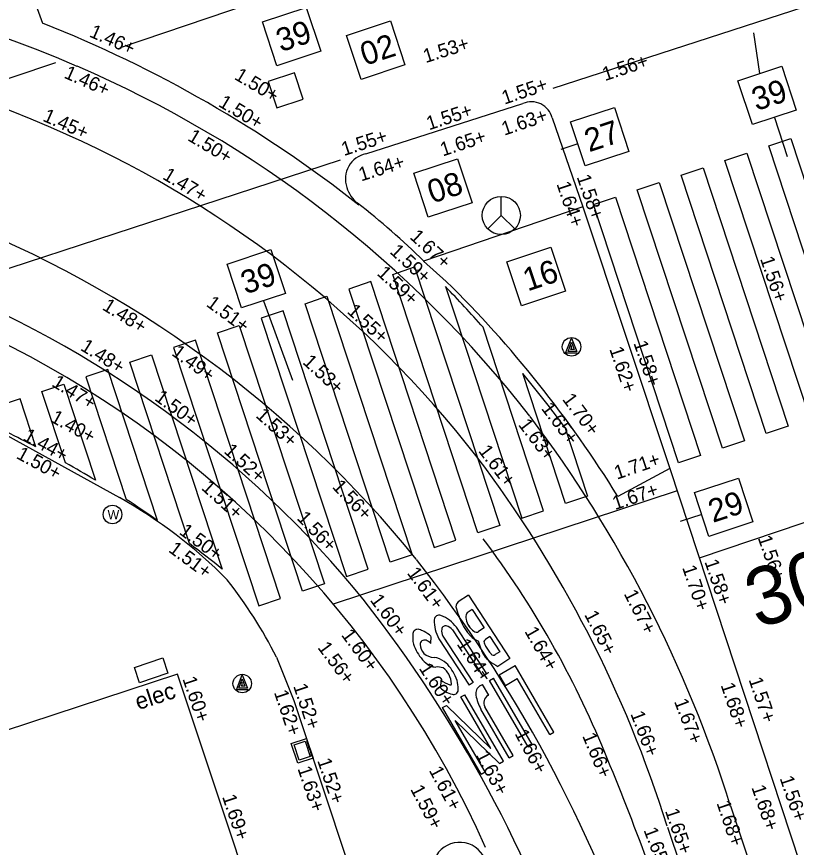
# Model space of a CAD drawing. Extents: x 122462 to 123306, y 485548 to 486417.
# Drawn here: x 122804.23 to 122821.1, y 486155.15 to 486173.11 of the extents above; entities that cross this region are included whole.
import ezdxf

# ---------------------------------------------------------------- set-up
doc = ezdxf.new("R2010")
doc.units = 0
for name, color, linetype in [('B-WE-IE-MEUBILAIR_ELECTRAKAST', 7, 'Continuous'), ('B-WE-OG-HOOGTEPUNT-S', 7, 'Continuous'), ('B-WE-OG-TOPOKAART-G', 7, 'Continuous'), ('iba7-verkeersbord blauw', 7, 'Continuous'), ('V markering 1-1 10 cm', 7, 'Continuous'), ('V markering figuratie', 7, 'Continuous'), ('V markering haaientanden', 7, 'Continuous'), ('V markering ononderbroken streep 10 cm', 7, 'Continuous'), ('V materiaalscheiding algemeen', 7, 'Continuous'), ('V meubilair ANWB paal', 7, 'Continuous'), ('V meubilair verkeersbord', 7, 'Continuous'), ('V Rails', 7, 'Continuous'), ('V riool putdeksel', 7, 'Continuous'), ('V riool trottoirkolk', 7, 'Continuous'), ('V RWS-band 115-225x250 mm specie', 7, 'Continuous'), ('V trottoirband 180-200x250 mm specie', 7, 'Continuous'), ('X-WE-AL-TEKENBLAD-S', 7, 'Continuous')]:
    doc.layers.add(name, color=color, linetype=linetype)

msp = doc.modelspace()

# ---------------------------------------------------------------- linework, layer by layer
at = {"layer": 'B-WE-IE-MEUBILAIR_ELECTRAKAST'}
for p, q in [((122806.779, 486159.039), (122807.397, 486159.243)), ((122807.397, 486159.243), (122807.505, 486158.911)), ((122806.888, 486158.707), (122806.779, 486159.039)), ((122807.505, 486158.911), (122806.888, 486158.707))]:
    msp.add_line(p, q, dxfattribs=at)
at = {"layer": 'B-WE-OG-TOPOKAART-G'}
msp.add_lwpolyline([(122810.445, 486142.778), (122812.82, 486143.569), (122807.709, 486158.89), (122801.277, 486156.78)], dxfattribs=at)
at = {"layer": 'iba7-verkeersbord blauw'}
msp.add_circle((122806.305, 486162.345), 0.2, dxfattribs=at)
at = {"layer": 'V markering 1-1 10 cm'}
msp.add_lwpolyline([(122811.233, 486170.007), (122798.828, 486165.954)], dxfattribs=at)
at = {"layer": 'V markering figuratie'}
for p, q in [((122814.005, 486160.601), (122813.781, 486160.455)), ((122814.005, 486160.601), (122814.903, 486159.228)), ((122814.089, 486160.288), (122813.981, 486160.218)), ((122814.089, 486160.288), (122814.347, 486159.893)), ((122813.743, 486159.905), (122814.4, 486158.901)), ((122814.347, 486159.893), (122814.226, 486159.814)), ((122813.191, 486159.556), (122813.196, 486159.71)), ((122813.452, 486159.714), (122814.108, 486158.709)), ((122813.66, 486159.851), (122814.317, 486158.847)), ((122814.471, 486159.704), (122814.372, 486159.639)), ((122814.471, 486159.704), (122814.682, 486159.378)), ((122813.368, 486159.659), (122814.024, 486158.654)), ((122814.682, 486159.378), (122814.587, 486159.316)), ((122814.903, 486159.228), (122814.645, 486159.06)), ((122814.669, 486158.881), (122815.013, 486159.08)), ((122815.85, 486157.64), (122815.013, 486159.08)), ((122814.4, 486158.901), (122814.317, 486158.847)), ((122814.459, 486158.758), (122814.545, 486158.808)), ((122815.382, 486157.368), (122814.545, 486158.808)), ((122814.805, 486158.647), (122814.669, 486158.881)), ((122814.805, 486158.647), (122815.063, 486158.797)), ((122815.765, 486157.59), (122815.063, 486158.797)), ((122813.406, 486158.764), (122813.398, 486158.595)), ((122814.108, 486158.709), (122814.024, 486158.654)), ((122814.264, 486158.645), (122814.309, 486158.671)), ((122814.445, 486158.438), (122814.309, 486158.671)), ((122815.297, 486157.318), (122814.459, 486158.758)), ((122813.841, 486158.399), (122813.926, 486158.448)), ((122814.763, 486157.008), (122813.926, 486158.448)), ((122814.426, 486158.427), (122814.445, 486158.438)), ((122814.49, 486157.282), (122813.841, 486158.399)), ((122813.445, 486158.169), (122813.528, 486158.217)), ((122814.282, 486156.728), (122813.445, 486158.169)), ((122814.49, 486157.282), (122813.528, 486158.217)), ((122814.89, 486157.081), (122814.277, 486158.136)), ((122814.975, 486157.131), (122814.362, 486158.186)), ((122814.68, 486156.959), (122813.72, 486157.892)), ((122814.368, 486156.778), (122813.72, 486157.892)), ((122815.765, 486157.59), (122815.85, 486157.64)), ((122815.297, 486157.318), (122815.382, 486157.368)), ((122814.68, 486156.959), (122814.763, 486157.008)), ((122814.89, 486157.081), (122814.975, 486157.131)), ((122814.282, 486156.728), (122814.368, 486156.778))]:
    msp.add_line(p, q, dxfattribs=at)
for points in [[(122822.346, 486164.731), (122820.504, 486170.318), (122820.978, 486170.476), (122822.82, 486164.889)], [(122821.398, 486164.414), (122819.555, 486170.001), (122820.03, 486170.159), (122821.872, 486164.572)], [(122820.449, 486164.097), (122818.607, 486169.684), (122819.081, 486169.842), (122820.923, 486164.255)], [(122819.501, 486163.78), (122817.658, 486169.367), (122818.133, 486169.525), (122819.975, 486163.938)], [(122818.552, 486163.463), (122816.71, 486169.05), (122817.184, 486169.208), (122819.026, 486163.621)], [(122814.21, 486161.951), (122812.368, 486167.538), (122812.842, 486167.697), (122814.685, 486162.11)], [(122811.42, 486167.221), (122813.262, 486161.634), (122813.736, 486161.793), (122811.894, 486167.38)], [(122812.313, 486161.317), (122810.471, 486166.904), (122810.945, 486167.063), (122812.788, 486161.476)], [(122809.523, 486166.588), (122811.365, 486161.001), (122811.839, 486161.159), (122809.997, 486166.746)], [(122810.416, 486160.684), (122808.574, 486166.271), (122809.049, 486166.429), (122810.891, 486160.842)], [(122807.626, 486165.954), (122809.468, 486160.367), (122809.942, 486160.525), (122808.1, 486166.112)]]:
    msp.add_lwpolyline(points, close=True, dxfattribs=at)
for points in [[(122813.508, 486167.274), (122815.159, 486162.268), (122815.633, 486162.427), (122814.325, 486166.394)], [(122807.97, 486161.717), (122806.677, 486165.637), (122807.152, 486165.795), (122808.679, 486161.162)], [(122807.278, 486162.218), (122806.203, 486165.478), (122805.729, 486165.32), (122806.602, 486162.672)], [(122816.091, 486164.231), (122816.581, 486162.744), (122816.107, 486162.585), (122815.181, 486165.394)], [(122805.288, 486163.464), (122804.78, 486165.003), (122805.255, 486165.161), (122805.939, 486163.086)], [(122804.647, 486163.81), (122804.306, 486164.844), (122803.832, 486164.686), (122804.017, 486164.126)]]:
    msp.add_lwpolyline(points, dxfattribs=at)
for centre, radius, start, end in [((122790.834, 486145.409), 31.499, 41.7743, 43.9578), ((122790.834, 486145.409), 31.499, 36.6934, 39.3801), ((122793.654, 486142.673), 23.824, 62.5212, 64.2182), ((122793.654, 486142.673), 23.824, 58.9603, 60.771), ((122793.654, 486142.673), 23.824, 55.1209, 57.0806), ((122793.654, 486142.673), 23.824, 50.9021, 53.0674), ((122813.866, 486160.355), 0.13, 130.2044, 201.7441), ((122815.938, 486160.955), 2.287, 196.4523, 201.7405), ((122813.964, 486160.022), 0.698, 176.115, 211.3596), ((122813.375, 486160.059), 0.109, 72.1477, 174.6458), ((122813.171, 486159.506), 0.698, 34.8339, 70.0785), ((122815.334, 486160.69), 1.628, 200.9537, 208.2212), ((122814.15, 486160.119), 0.199, 153.3445, 191.8719), ((122814.394, 486160.172), 0.448, 192.1555, 212.2665), ((122813.996, 486160.196), 0.0256, 123.4302, 153.3445), ((122813.508, 486159.856), 0.0816, 71.44, 175.2165), ((122813.476, 486159.708), 0.233, 37.7791, 75.6405), ((122814.889, 486160.507), 1.15, 210.6597, 220.942), ((122814.433, 486160.226), 0.51, 214.9747, 232.6342), ((122813.394, 486159.684), 0.595, 171.6022, 193.6008), ((122812.906, 486159.761), 0.101, 72.0219, 174.3362), ((122812.848, 486159.483), 0.384, 58.7817, 76.6476), ((122812.648, 486159.071), 0.842, 49.4271, 61.6531), ((122813.657, 486159.824), 0.233, 170.2725, 208.1339), ((122814.359, 486160.014), 0.428, 217.5747, 251.9484), ((122814.179, 486159.884), 0.0849, 229.3337, 303.5616), ((122813.623, 486159.797), 0.846, 197.3862, 210.8175), ((122813.057, 486159.534), 0.0964, 71.3983, 180.6349), ((122813.268, 486159.548), 0.307, 182.7741, 222.2592), ((122812.941, 486159.295), 0.362, 46.2045, 65.9719), ((122811.982, 486158.843), 2.37, 14.4022, 18.7882), ((122814.408, 486159.582), 0.0675, 121.909, 167.7229), ((122814.805, 486159.706), 0.476, 193.2255, 205.8502), ((122813.737, 486159.855), 0.974, 210.3227, 221.8314), ((122813.28, 486159.617), 0.365, 228.9599, 267.1101), ((122814.75, 486159.577), 0.493, 196.9472, 233.3), ((122815.001, 486159.804), 0.695, 206.1216, 223.2043), ((122813.505, 486159.63), 0.651, 220.7065, 238.69), ((122813.224, 486158.841), 0.413, 51.2717, 84.7982), ((122813.064, 486158.612), 0.692, 36.3276, 52.8145), ((122815.282, 486160.268), 1.366, 232.7346, 242.199), ((122814.548, 486159.373), 0.0697, 220.2342, 304.4683), ((122813.299, 486159.368), 0.322, 245.8091, 270.6339), ((122813.335, 486158.697), 0.35, 69.7297, 95.3518), ((122813.288, 486158.745), 0.327, 24.6134, 59.0664), ((122812.829, 486158.444), 0.981, 24.6208, 36.0826), ((122813.111, 486158.635), 0.534, 5.4213, 27.3838), ((122813.209, 486158.596), 0.573, 6.1755, 26.6295), ((122813.811, 486159.292), 0.666, 232.4802, 251.7493), ((122813.612, 486158.689), 0.0305, 251.2599, 354.9973), ((122813.204, 486158.571), 0.581, 357.2377, 8.5295), ((122814.364, 486158.471), 0.201, 120.1695, 190.1275), ((122813.843, 486159.107), 0.678, 229.0189, 240.597), ((122813.883, 486159.224), 0.8, 242.2305, 253.2995), ((122813.686, 486158.551), 0.0987, 250.6138, 355.6868), ((122815.069, 486158.597), 0.916, 190.1289, 210.1695), ((122814.515, 486158.275), 0.176, 120.1695, 210.1695)]:
    msp.add_arc(centre, radius, start, end, dxfattribs=at)
at = {"layer": 'V markering haaientanden'}
for points in [[(122815.839, 486171.566), (122825.165, 486174.59)], [(122809.772, 486173.563), (122806.472, 486172.433)]]:
    msp.add_lwpolyline(points, dxfattribs=at)
at = {"layer": 'V markering ononderbroken streep 10 cm'}
msp.add_lwpolyline([(122796.786, 486169.34), (122805.08, 486172.122)], dxfattribs=at)
for centre, radius, start, end in [((122797.619, 486149.245), 20.91, 22.3632, 36.9681), ((122746.081, 486128.041), 76.639, 18.61709, 22.36324)]:
    msp.add_arc(centre, radius, start, end, dxfattribs=at)
at = {"layer": 'V materiaalscheiding algemeen'}
msp.add_line((122818.523, 486162.855), (122811.081, 486160.409), dxfattribs=at)
for points in [[(122820.373, 486178.699), (122819.656, 486178.534), (122819.692, 486178.438), (122804.62, 486173.448), (122804.792, 486172.968)], [(122819.003, 486161.406), (122821.801, 486162.349)]]:
    msp.add_lwpolyline(points, dxfattribs=at)
for centre, radius, start, end in [((122794.859, 486147.77), 27.085, 51.7216, 68.4862), ((122793.815, 486145.927), 22.535, 24.1472, 99.0789)]:
    msp.add_arc(centre, radius, start, end, dxfattribs=at)
at = {"layer": 'V meubilair ANWB paal'}
for q in [(122814.716, 486169.224), (122814.424, 486168.519), (122815.008, 486168.519)]:
    msp.add_line((122814.716, 486168.811), q, dxfattribs=at)
msp.add_circle((122814.716, 486168.811), 0.413, dxfattribs=at)
at = {"layer": 'V meubilair verkeersbord'}
for points in [[(122816.361, 486165.833), (122816.109, 486165.833), (122816.236, 486166.156), (122816.35, 486165.871), (122816.165, 486165.871), (122816.236, 486166.071), (122816.292, 486165.911), (122816.223, 486165.911), (122816.236, 486165.951), (122816.237, 486166.001)], [(122809.237, 486158.551), (122808.985, 486158.551), (122809.112, 486158.874), (122809.226, 486158.589), (122809.041, 486158.589), (122809.112, 486158.789), (122809.168, 486158.629), (122809.099, 486158.629), (122809.112, 486158.669), (122809.113, 486158.719)]]:
    msp.add_lwpolyline(points, dxfattribs=at)
for centre in [(122816.236, 486165.971), (122809.112, 486158.689)]:
    msp.add_circle(centre, 0.2, dxfattribs=at)
at = {"layer": 'V Rails'}
for p, q in [((122819.673, 486156.047), (122836.339, 486106.728)), ((122818.309, 486155.586), (122834.974, 486106.268))]:
    msp.add_line(p, q, dxfattribs=at)
for centre, radius, start, end in [((122795.822, 486149.654), 24.402, 66.5251, 103.0007), ((122795.822, 486149.654), 22.962, 66.5251, 103.0007), ((122795.758, 486149.261), 24.788, 37.8464, 66.7583), ((122795.758, 486149.261), 23.348, 37.8464, 66.7583), ((122793.991, 486146.126), 24.276, 38.9361, 68.8275), ((122793.991, 486146.126), 22.836, 38.9361, 68.8275), ((122793.305, 486147.787), 27.632, 17.3592, 37.1191), ((122793.305, 486147.787), 26.192, 17.3592, 37.1191), ((122789.32, 486142.851), 29.97, 18.4811, 38.1761), ((122789.32, 486142.851), 28.53, 18.4811, 38.1761)]:
    msp.add_arc(centre, radius, start, end, dxfattribs=at)
at = {"layer": 'V riool putdeksel'}
msp.add_lwpolyline([(122809.859, 486171.14), (122810.43, 486171.326), (122810.243, 486171.897), (122809.673, 486171.71)], close=True, dxfattribs=at)
at = {"layer": 'V riool trottoirkolk'}
for p, q in [((122810.171, 486157.394), (122810.504, 486157.504)), ((122810.313, 486156.966), (122810.171, 486157.394)), ((122810.504, 486157.504), (122810.645, 486157.077)), ((122810.508, 486157.442), (122810.523, 486157.398)), ((122810.519, 486157.456), (122810.515, 486157.455)), ((122810.523, 486157.398), (122810.533, 486157.366)), ((122810.551, 486157.361), (122810.546, 486157.36)), ((122810.548, 486157.323), (122810.573, 486157.248)), ((122810.559, 486157.338), (122810.554, 486157.336)), ((122810.59, 486157.243), (122810.585, 486157.241)), ((122810.587, 486157.205), (122810.612, 486157.129)), ((122810.598, 486157.219), (122810.593, 486157.217)), ((122810.645, 486157.077), (122810.313, 486156.966)), ((122810.63, 486157.124), (122810.625, 486157.123))]:
    msp.add_line(p, q, dxfattribs=at)
msp.add_lwpolyline([(122810.345, 486157.03), (122810.235, 486157.362), (122810.472, 486157.441), (122810.582, 486157.108)], close=True, dxfattribs=at)
for centre, start, end in [((122810.518, 486157.445), 108.3529, 198.3529), ((122810.543, 486157.369), 198.3529, 288.3529), ((122810.557, 486157.327), 108.3529, 198.3529), ((122810.582, 486157.251), 198.3529, 288.3529), ((122810.597, 486157.208), 108.3529, 198.3529), ((122810.622, 486157.132), 198.3529, 288.3529)]:
    msp.add_arc(centre, 0.01, start, end, dxfattribs=at)
at = {"layer": 'V RWS-band 115-225x250 mm specie'}
msp.add_lwpolyline([(122818.364, 486163.338), (122821.173, 486154.804), (122825.19, 486142.715)], dxfattribs=at)
at = {"layer": 'V trottoirband 180-200x250 mm specie'}
for points in [[(122811.789, 486170.143), (122815.183, 486171.232)], [(122815.817, 486170.92), (122816.481, 486168.998), (122818.364, 486163.338)], [(122816.481, 486168.998), (122813.037, 486167.824)], [(122813.527, 486167.386), (122813.037, 486167.824)], [(122803.794, 486164.177), (122806.455, 486162.709)], [(122818.364, 486163.338), (122817.238, 486162.734)], [(122809.854, 486159.259), (122810.231, 486158.325), (122812.595, 486151.199), (122817.313, 486137.073), (122821.012, 486126.049)]]:
    msp.add_lwpolyline(points, dxfattribs=at)
for centre, radius, start, end in [((122815.368, 486170.807), 0.463, 14.0813, 113.5139), ((122811.893, 486169.603), 0.55, 100.8989, 199.6454), ((122812.028, 486169.609), 0.68, 196.3051, 231.4619), ((122802.461, 486157.175), 15.009, 45.1981, 52.4697), ((122796.078, 486149.66), 24.873, 31.7097, 45.4505), ((122801.32, 486153.56), 10.492, 44.6338, 60.6961), ((122800.918, 486154.728), 10.019, 26.8864, 38.2509), ((122813.818, 486154.661), 0.593, 17.3137, 201.8508)]:
    msp.add_arc(centre, radius, start, end, dxfattribs=at)
at = {"layer": 'X-WE-AL-TEKENBLAD-S'}
for p, q in [((122820.311, 486171.882), (122820.183, 486172.76)), ((122820.625, 486170.932), (122820.903, 486170.089)), ((122816.372, 486170.359), (122816.001, 486170.237)), ((122809.571, 486166.968), (122810.202, 486165.251)), ((122819.052, 486162.344), (122818.587, 486162.191))]:
    msp.add_line(p, q, dxfattribs=at)
for points in [[(122809.547, 486172.999), (122810.497, 486173.312), (122810.81, 486172.363), (122809.861, 486172.05)], [(122811.368, 486172.703), (122812.318, 486173.017), (122812.631, 486172.067), (122811.682, 486171.754)], [(122819.836, 486171.725), (122820.786, 486172.038), (122821.099, 486171.089), (122820.15, 486170.776)], [(122816.216, 486170.834), (122817.165, 486171.148), (122817.479, 486170.198), (122816.529, 486169.885)], [(122812.822, 486169.724), (122813.772, 486170.038), (122814.085, 486169.088), (122813.136, 486168.775)], [(122808.783, 486167.761), (122809.732, 486168.074), (122810.046, 486167.125), (122809.096, 486166.811)], [(122814.839, 486167.81), (122815.788, 486168.123), (122816.102, 486167.174), (122815.152, 486166.86)], [(122818.895, 486162.819), (122819.845, 486163.132), (122820.158, 486162.183), (122819.209, 486161.869)]]:
    msp.add_lwpolyline(points, close=True, dxfattribs=at)

# ---------------------------------------------------------------- texts
at = {"layer": 'B-WE-IE-MEUBILAIR_ELECTRAKAST'}
msp.add_text('elec', height=0.36, rotation=18.1687, dxfattribs=at).set_placement((122806.862, 486158.112))
at = {"layer": 'B-WE-OG-HOOGTEPUNT-S'}
for s, rotation, p in [('1.46+', 336.0664, (122805.786, 486172.685)), ('1.53+', 17.4578, (122813.08, 486172.105)), ('1.56+', 18.3223, (122816.96, 486171.715)), ('1.46+', 336.0664, (122805.237, 486171.795)), ('1.50+', 329.0104, (122808.922, 486171.77)), ('1.55+', 18.6066, (122814.785, 486171.206)), ('1.50+', 329.0104, (122808.578, 486171.184)), ('1.45+', 336.0664, (122804.777, 486170.864)), ('1.55+', 18.0942, (122813.152, 486170.651)), ('1.63+', 18.6066, (122814.781, 486170.535)), ('1.50+', 329.0104, (122807.912, 486170.447)), ('1.55+', 17.8392, (122811.312, 486170.095)), ('1.65+', 18.0942, (122813.451, 486170.086)), ('1.64+', 17.3763, (122811.685, 486169.546)), ('1.47+', 329.0104, (122807.369, 486169.613)), ('1.58+', 288.5923, (122816.344, 486169.647)), ('1.64+', 288.5923, (122815.907, 486169.495)), ('1.67+', 317.0813, (122812.719, 486168.327)), ('1.59+', 317.0813, (122812.287, 486168.01)), ('1.56+', 288.5923, (122820.313, 486167.874)), ('1.59+', 317.0813, (122812.009, 486167.539)), ('1.48+', 328.241, (122806.065, 486166.788)), ('1.51+', 323.6274, (122808.315, 486166.864)), ('1.55+', 317.0813, (122811.363, 486166.717)), ('1.48+', 328.241, (122805.592, 486165.912)), ('1.49+', 323.6274, (122807.567, 486165.803)), ('1.58+', 288.5923, (122817.573, 486166.052)), ('1.62+', 288.5923, (122817.051, 486165.923)), ('1.53+', 317.0813, (122810.401, 486165.621)), ('1.47+', 328.241, (122804.971, 486165.135)), ('1.50+', 323.6274, (122807.197, 486164.83)), ('1.70+', 306.9268, (122816.024, 486164.833)), ('1.65+', 306.9268, (122815.568, 486164.636)), ('1.40+', 331.3327, (122804.942, 486164.363)), ('1.53+', 317.7458, (122809.388, 486164.463)), ('1.63+', 306.9268, (122815.071, 486164.284)), ('1.44+', 331.1157, (122804.348, 486163.967)), ('1.52+', 317.7458, (122808.698, 486163.693)), ('1.61+', 306.9268, (122814.208, 486163.717)), ('1.50+', 331.1157, (122804.205, 486163.572)), ('1.71+', 18.6184, (122817.219, 486163.097)), ('1.51+', 317.7458, (122808.211, 486162.9)), ('1.56+', 313.4089, (122811.042, 486162.933)), ('1.67+', 18.6184, (122817.179, 486162.438)), ('1.56+', 313.4089, (122810.279, 486162.252)), ('1.50+', 323.3514, (122807.73, 486161.936)), ('1.56+', 288.6664, (122820.263, 486161.841)), ('1.51+', 323.3514, (122807.498, 486161.552)), ('1.58+', 288.5967, (122819.109, 486161.324)), ('1.61+', 306.4676, (122812.666, 486161.076)), ('1.70+', 288.5967, (122818.627, 486161.197)), ('1.60+', 306.4676, (122811.865, 486160.491)), ('1.67+', 296.7346, (122817.361, 486160.632)), ('1.65+', 296.7346, (122816.506, 486160.181)), ('1.64+', 299.8028, (122815.21, 486159.819)), ('1.60+', 306.4676, (122811.243, 486159.737)), ('1.56+', 306.4676, (122810.731, 486159.464)), ('1.64+', 303.2405, (122813.743, 486159.543)), ('1.60+', 303.2405, (122812.924, 486159.018)), ('1.60+', 288.469, (122807.816, 486158.792)), ('1.57+', 288.5967, (122820.063, 486158.775)), ('1.52+', 288.469, (122810.211, 486158.637)), ('1.68+', 288.5967, (122819.459, 486158.657)), ('1.62+', 288.469, (122809.796, 486158.499)), ('1.67+', 290.8334, (122818.45, 486158.303)), ('1.66+', 290.8334, (122817.505, 486158.035)), ('1.66+', 297.5935, (122814.999, 486157.608)), ('1.66+', 292.313, (122816.463, 486157.559)), ('1.63+', 297.5935, (122814.159, 486157.144)), ('1.52+', 288.469, (122810.732, 486157.025)), ('1.63+', 288.469, (122810.305, 486156.851)), ('1.61+', 297.5935, (122813.145, 486156.812)), ('1.56+', 288.6561, (122820.736, 486156.643)), ('1.59+', 297.5935, (122812.741, 486156.407)), ('1.68+', 288.6561, (122820.125, 486156.444)), ('1.69+', 288.469, (122808.674, 486156.242)), ('1.68+', 288.6561, (122819.369, 486156.106)), ('1.65+', 288.6561, (122818.255, 486155.936)), ('1.65+', 290.7677, (122817.79, 486155.521))]:
    msp.add_text(s, height=0.3, rotation=rotation, dxfattribs=at).set_placement(p)
at = {"layer": 'iba7-verkeersbord blauw'}
msp.add_text('W', height=0.2, dxfattribs=at).set_placement((122806.199, 486162.24))
at = {"layer": 'V markering figuratie'}
msp.add_text('30', height=1.26, rotation=18.2384, dxfattribs=at).set_placement((122820.258, 486159.867))
at = {"layer": 'X-WE-AL-TEKENBLAD-S'}
for s, p in [('39', (122809.946, 486172.341)), ('02', (122811.766, 486172.045)), ('39', (122820.235, 486171.067)), ('27', (122816.615, 486170.176)), ('08', (122813.22, 486169.066)), ('39', (122809.181, 486167.103)), ('16', (122815.285, 486167.167)), ('29', (122819.294, 486162.161))]:
    msp.add_text(s, height=0.5, rotation=18.2603, dxfattribs=at).set_placement(p)

doc.saveas('drawing.dxf')
